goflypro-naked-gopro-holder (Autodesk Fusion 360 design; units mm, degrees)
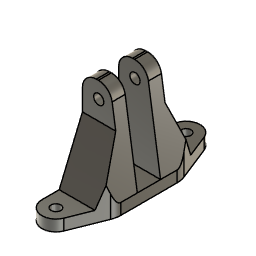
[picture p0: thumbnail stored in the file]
sketch "Skizze1" plane through (0, 0, 0) normal (0, 0, 1) x axis (1, 0, 0)
  line L1 (10, -1) -> (10.0015, -1)
  line L2 (7, -26) -> (7, 2)
  line L3 (12.7891, 3.1049) -> (16, -5)
  line L4 (16, -19) -> (16, -5)
  line L5 (12.7891, -27.1049) -> (16, -19)
  line L6 (7, -6.7) -> (12, -6.7)
  line L7 (7, -17.3) -> (7, -6.7)
  line L8 (12, -17.3) -> (7, -17.3)
  line L9 (7, -9.5) -> (12, -9.5)
  line L10 (7, -14.5) -> (12, -14.5)
  line L11 (16, -6.7) -> (12, -6.7)
  line L12 (16, -9.5) -> (12, -9.5)
  line L13 (16, -14.5) -> (12, -14.5)
  line L14 (16, -17.3) -> (12, -17.3)
  circle C1 centre (10, 2) radius 1.05
  circle C2 centre (10, -26) radius 1.05
  circle C3 centre (10, -26) radius 3
  circle C4 centre (10, 2) radius 3
  point P7 (7, 2)
  point P8 (7, -26)
  point P10 (12.7891, 3.1049)
  point P12 (12.7891, -27.1049)
  point P18 (7, -9.5)
  point P20 (7, -14.5)
  point P22 (16, -6.7)
  point P23 (16, -9.5)
  point P24 (16, -14.5)
  point P25 (16, -17.3)
  point P14 (12, -6.7)
  point P17 (12, -17.3)
  concentric C2 C3
  concentric C1 C4
  coincident C4 P7
  coincident C3 P8
  tangent C3 L2
  coincident C4 P10
  tangent C4 L3
  coincident C3 P12
  tangent C3 L5
  horizontal L6
  vertical L7
  horizontal L8
  coincident L7 P18
  perpendicular L7 L9
  coincident L2 P20
  perpendicular L2 L10
  coincident L4 P22
  perpendicular L4 L11
  coincident L4 P23
  perpendicular L4 L12
  coincident L4 P24
  perpendicular L4 L13
  coincident L4 P25
  perpendicular L4 L14
  dimension "d4" diameter C1 = 2.1
  dimension "d12" diameter C2 = 2.1
  dimension "d14" diameter C3 = 6
  dimension "d16" diameter C4 = 6
  dimension "d73" distance P14 P17 = 10.6
extrude "Extrusion3" new body sketch "Skizze1" profile of C1 C2 C3 C4 L1 L2 L3 L4 L5 L6 L7 L8 L9 along normal blind 2.4 bodies "GoFlyPro - naked-gopro-holder"
extrude "Extrusion8" add sketch "Skizze1" profile of L2 L4 L6 L7 L8 L9 L10 L11 L12 L13 L14 along normal blind 22
sketch "Skizze7" plane through (0, -6.7, 0) normal (0, 1, 0) x axis (-1, 0, 0)
  line L1 (-7, 2.4) -> (-16, 2.4)
  line L2 (-7, 22) -> (-7, 2.4)
  line L3 (-16, 22) -> (-7, 22)
  line L4 (-16, 2.4) -> (-16, 22)
  circle C1 centre (-10.5, 18.5) radius 1.1
  circle C2 centre (-10.5, 18.5) radius 2.1
  concentric C1 C2
  dimension "d79" diameter C1 = 2.2
  dimension "d80" diameter C2 = 4.2
extrude "Extrusion9" cut sketch "Skizze7" profile of C1 against normal blind 11
extrude "Extrusion10" cut sketch "Skizze7" profile of C1 C2 against normal blind 0.4
chamfer "Fase3" distance 3 distance 19.6
fillet "Abrundung18" radius 3
chamfer "Fase4" distance 5 distance 12
fillet "Abrundung17" radius 5
named bodies: "GoFlyPro - naked-gopro-holder"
